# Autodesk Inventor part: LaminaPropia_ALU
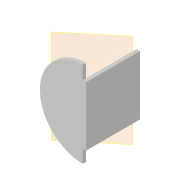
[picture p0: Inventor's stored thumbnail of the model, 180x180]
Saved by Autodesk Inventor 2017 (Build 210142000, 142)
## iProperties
Part Number: LaminaPropia_ALU
Material: Generisch
Document SubType Name: Modeling
Designer: gabriel
Density: 1 g/cm^3
Appearance: Vorgabe
Author: gabriel
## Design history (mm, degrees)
sketch "Skizze1"
  geometry: L1 (0, 19.5)-(0, -19.5); A1 r 19.5 centre (0, 0) between (0, -19.5) and (0, 19.5); 1 further point
  constraints: 2 end point, 2 point on circle, 1 centre point, 1 coincident, 1 vertical
  dimensions: "d0" = 19.5 distance of L1.start point (0, 0)
extrude "Extrusion1" new body sketch "Skizze1" distance "d1" = 1.6; taper "d2" = 0 deg
sketch "Skizze2"
  geometry: L1 (0, -19.5)-(0, 19.5) reference; L2 (0, -7.5)-(0, 7.5); A1 r 7.5 centre (0, 0) between (0, 7.5) and (0, -7.5); 1 further point
  constraints: 2 end point, 2 point on circle, 1 centre point, 1 coincident, 1 collinear, 1 point on line
  dimensions: "d11" = 7.5 distance of L2.start point (0, 0)
extrude "Extrusion2" join sketch "Skizze2" distance "d3" = 19.53; taper "d4" = 0 deg
workplane "Arbeitsebene1"
sketch "Skizze3"
  geometry: L1 (-1.5, 0)-(18.508, 0); L2 (18.508, 0)-(18.508, -11); L3 (18.508, -11)-(-1.5, -11); L4 (-1.5, -11)-(-1.5, 0); 1 further point
  constraints: 8 end point, 2 parallel, 1 horizontal, 1 perpendicular
extrude "Extrusion3" cut sketch "Skizze3" distance "d6" = 10; taper "d7" = 0 deg
sketch "Skizze7"
  geometry: L1 (46.8, 0)-(-7.8, 0) reference; L2 (19.5, -4.226)-(19.5, 25.356) reference; L3 (39, 1.6)-(0, 1.6) reference; L4 (27, 1.6)-(27, 3.6); L5 (27, 3.6)-(28, 1.6); L6 (27, 1.6)-(28, 1.6); L7 (12, 21.13)-(27, 21.13) reference; L8 (27, 21.13)-(27, 1.6) reference; L9 (27, 1.6)-(39, 1.6) reference; L10 (39, 1.6)-(39, 0) reference; L11 (39, 0)-(0, 0) reference; L12 (0, 0)-(0, 1.6) reference; L13 (0, 1.6)-(12, 1.6) reference; L14 (12, 1.6)-(12, 21.13) reference; L15 (27, 1.6)-(27, 21.13) reference; 1 further point
  constraints: 6 end point, 3 point on line, 1 collinear, 1 vertical
  dimensions: "d16" = 2 distance of L4.start L4.end; "d28" = 1 distance from line of L4 L5.end
revolve "Umdrehung1" sketch "Skizze7" stored, may be unused: angle "d17" = 180 deg
sketch "Skizze8"
  geometry: L1 (23.4, 0)-(-3.9, 0) reference; L2 (0, -27.3)-(0, 27.3) reference; L3 (0, 19.5)-(0, -19.5) reference; L4 (0, 13.5)-(-1.6, 13.5); L5 (-1.6, 13.5)-(-1.6, -13.5); L6 (-1.6, -13.5)-(0, -13.5); L7 (0, -13.5)-(0, 13.5); 1 further point
  constraints: 8 end point, 2 parallel, 1 horizontal, 1 perpendicular, 1 point on line, 1 other
  dimensions: "d18" = 27 distance of L4.end L5.end; "d19" = 1.6 distance of L4.start L4.end
extrude "Extrusion5" join sketch "Skizze8" distance "d20" = 24.6; taper "d21" = 0 deg
fillet "Rundung3" dims "d23" = 1
fillet "Rundung2" dims "d22" = 1
node "Volumenkörper1"
node "Schnittkanten projizieren2"
other parameters: "d5" = 50 deg
